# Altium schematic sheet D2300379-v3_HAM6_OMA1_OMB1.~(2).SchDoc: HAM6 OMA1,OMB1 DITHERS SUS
size C; Engineer: L. Sanchez; Organization: LIGO Laboratory; Address1: California Institute of Technology; Address2: Massachusetts Institute of Technology; DocumentNumber: D2300379; Revision: v2; SheetNumber: 2; SheetTotal: 9
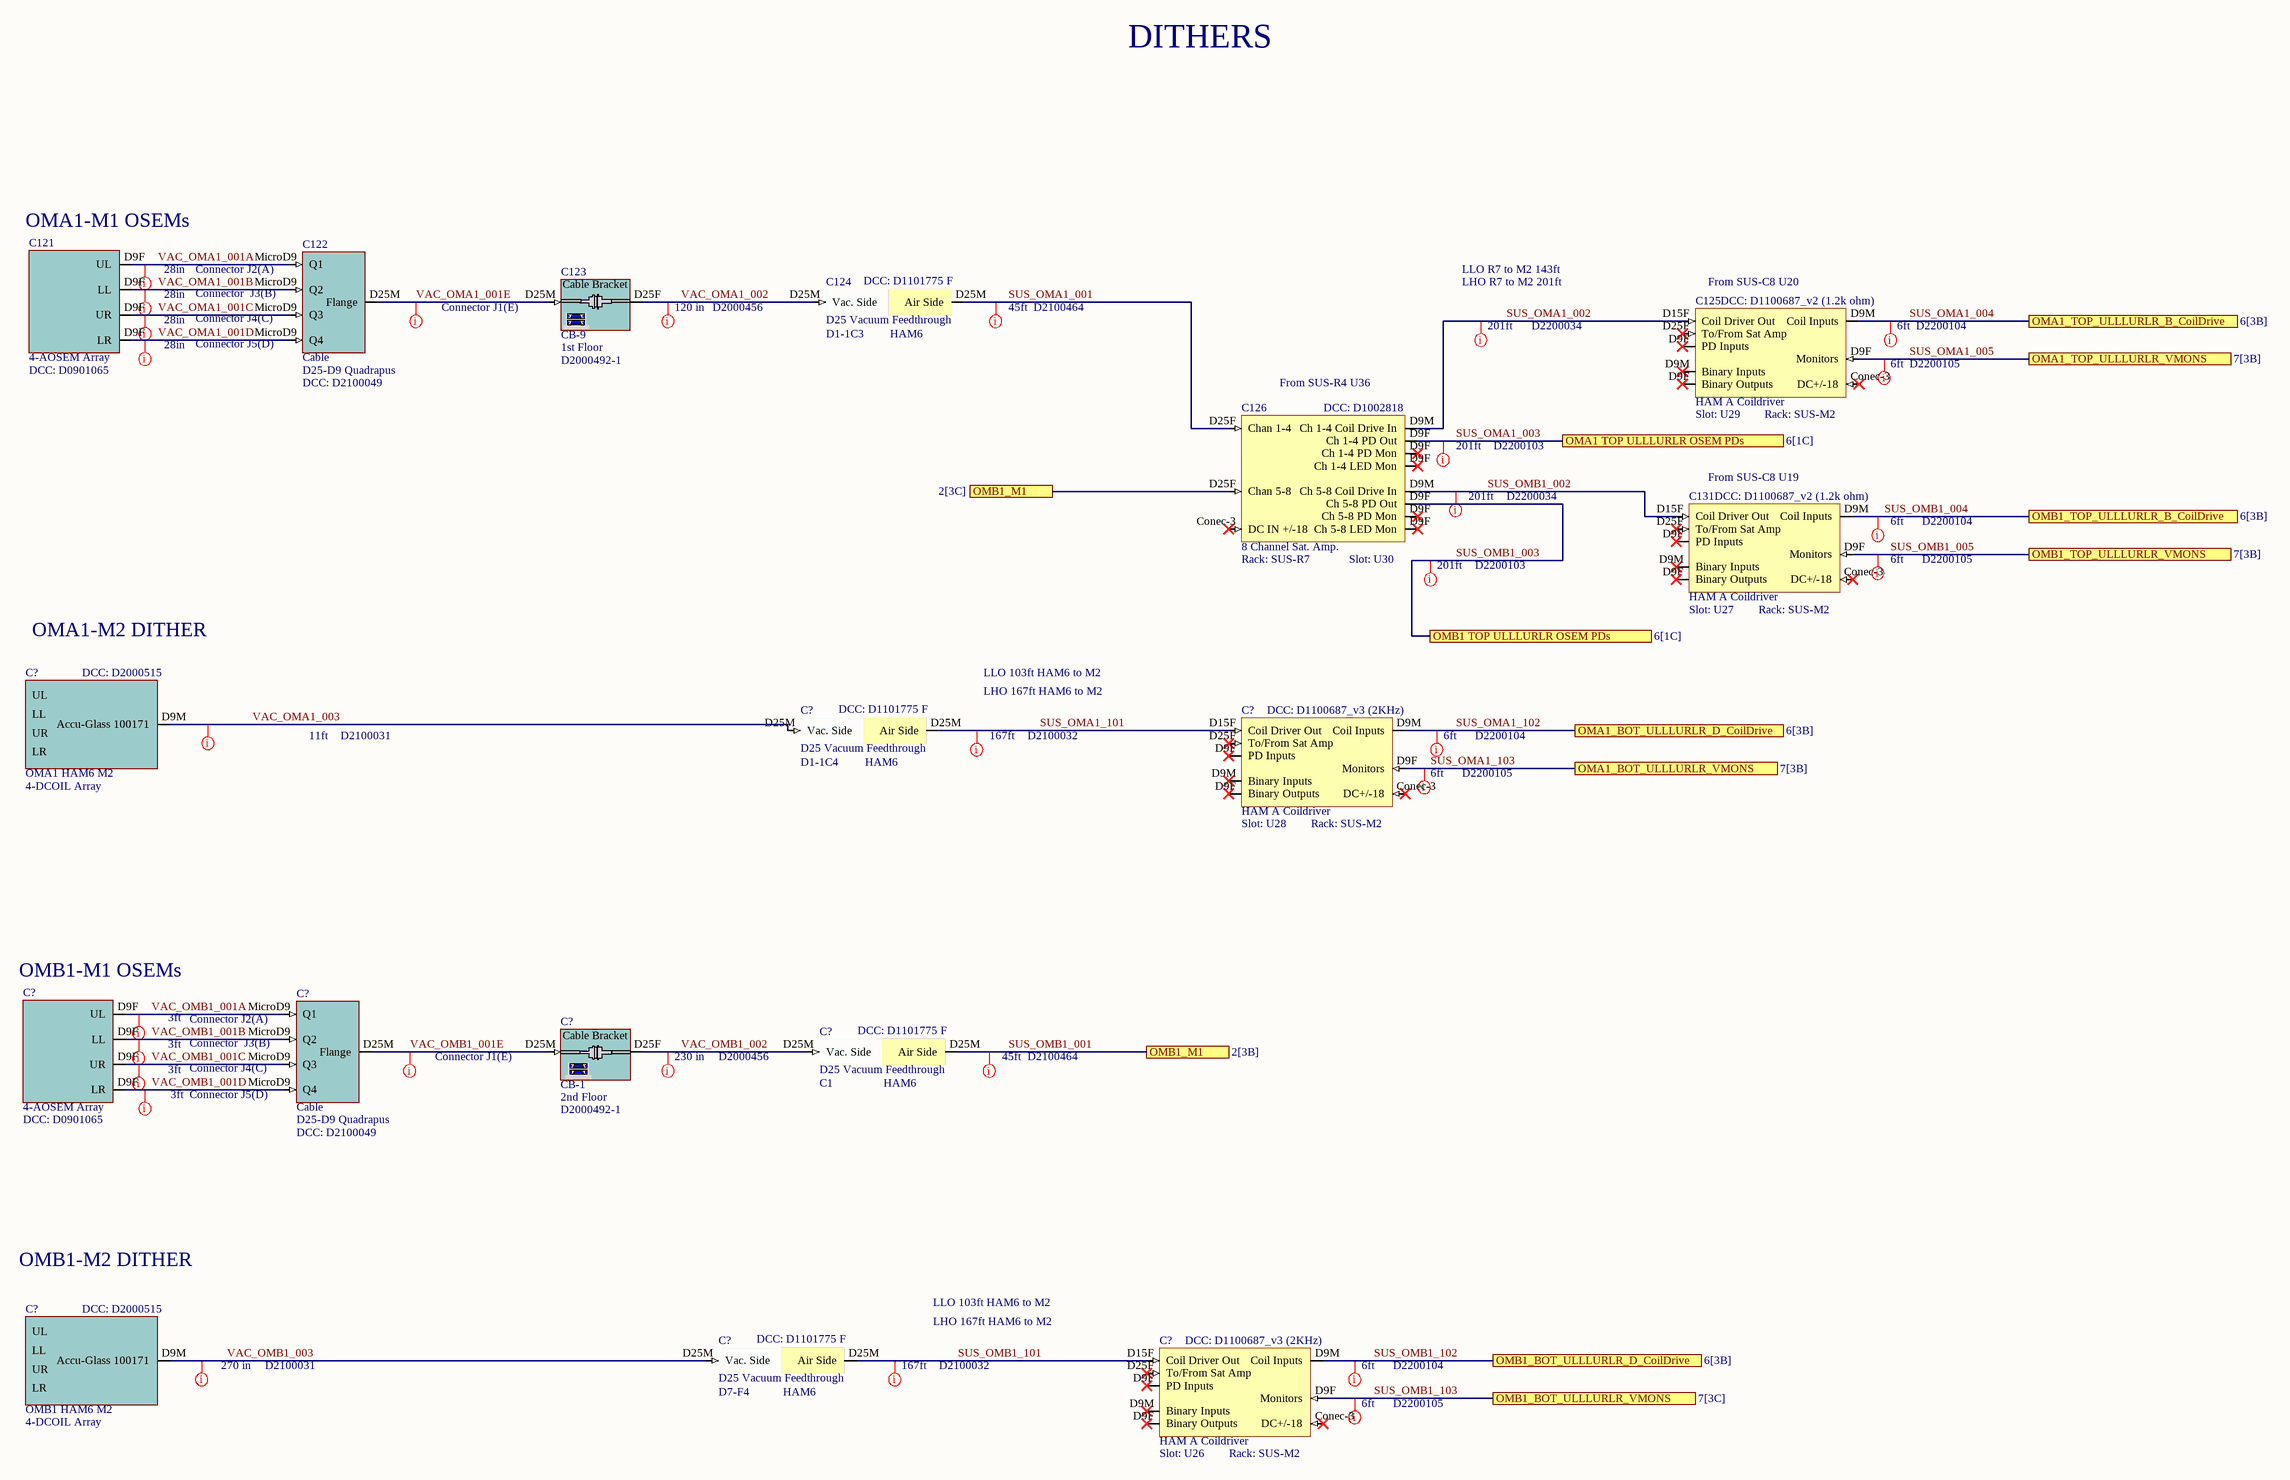
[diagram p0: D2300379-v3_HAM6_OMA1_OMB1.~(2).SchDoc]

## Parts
(Parts that share a designator on the sheet are numbered #1, #2 ... from top to bottom, then left to right.)
C121  4-AOSEM Array  DCC: D0901065
C122  Cable  value D25-D9 Quadrapus  DCC: D2100049
C123  Rack: CB-9  Slot: 1st Floor  DCC: D2000492-1  (hidden comment: Cable Bracket)
C124  D25 Vacuum Feedthrough  DCC: D1101775 F  Feedthrough: D1-1C3  Chamber: HAM6
C125  HAM A Coildriver  DCC: D1100687_v2 (1.2k ohm)  Rack: SUS-M2  Slot: U29
C126  8 Channel Sat. Amp.  DCC: D1002818  Rack: SUS-R7  Slot: U30
C131  HAM A Coildriver  DCC: D1100687_v2 (1.2k ohm)  Rack: SUS-M2  Slot: U27
C?#1  value 4-DCOIL Array  Rack: OMA1 HAM6 M2  DCC: D2000515  (hidden comment: Cable)
C?#2  D25 Vacuum Feedthrough  DCC: D1101775 F  Feedthrough: D1-1C4  Chamber: HAM6
C?#3  HAM A Coildriver  DCC: D1100687_v3 (2KHz)  Rack: SUS-M2  Slot: U28
C?#4  Rack: CB-1  Slot: 2nd Floor  DCC: D2000492-1  (hidden comment: Cable Bracket)
C?#5  D25 Vacuum Feedthrough  DCC: D1101775 F  Feedthrough: C1  Chamber: HAM6
C?#6  4-AOSEM Array  DCC: D0901065
C?#7  Cable  value D25-D9 Quadrapus  DCC: D2100049
C?#8  value 4-DCOIL Array  Rack: OMB1 HAM6 M2  DCC: D2000515  (hidden comment: Cable)
C?#9  D25 Vacuum Feedthrough  DCC: D1101775 F  Feedthrough: D7-F4  Chamber: HAM6
C?#10  HAM A Coildriver  DCC: D1100687_v3 (2KHz)  Rack: SUS-M2  Slot: U26

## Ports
OMA1 TOP ULLLURLR OSEM PDs (see 6[1C]), OMA1_BOT_ULLLURLR_D_CoilDrive (see 6[3B]), OMA1_BOT_ULLLURLR_VMONS (see 7[3B]), OMA1_TOP_ULLLURLR_B_CoilDrive (see 6[3B]), OMA1_TOP_ULLLURLR_VMONS (see 7[3B]), OMB1 TOP ULLLURLR OSEM PDs (see 6[1C]), OMB1_BOT_ULLLURLR_D_CoilDrive (see 6[3B]), OMB1_BOT_ULLLURLR_VMONS (see 7[3C]), OMB1_M1 (see 2[3B]), OMB1_M1 (see 2[3C]), OMB1_TOP_ULLLURLR_B_CoilDrive (see 6[3B]), OMB1_TOP_ULLLURLR_VMONS (see 7[3B])

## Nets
SUS_OMA1_001: C124.D25M(Air_Side) C126.D25F(Chan_1-4)
SUS_OMA1_002: C125.D15F(Coil_Driver_Out) C126.D9M(Ch_1-4_Coil_Drive_In)
SUS_OMA1_003: C126.D9F(Ch_1-4_PD_Out) ; port OMA1 TOP ULLLURLR OSEM PDs
SUS_OMA1_004: C125.D9M(Coil_Inputs) ; port OMA1_TOP_ULLLURLR_B_CoilDrive
SUS_OMA1_005: C125.D9F(PD_Inputs) ; port OMA1_TOP_ULLLURLR_VMONS
SUS_OMA1_101: C?#2.D25M(Air_Side) C?#3.D15F(Coil_Driver_Out)
SUS_OMA1_102: C?#3.D9M(Coil_Inputs) ; port OMA1_BOT_ULLLURLR_D_CoilDrive
SUS_OMA1_103: C?#3.D9F(PD_Inputs) ; port OMA1_BOT_ULLLURLR_VMONS
SUS_OMB1_001: C126.D25F(Chan_5-8) C?#5.D25M(Air_Side) ; port OMB1_M1
SUS_OMB1_002: C126.D9M(Ch_5-8_Coil_Drive_In) C131.D15F(Coil_Driver_Out)
SUS_OMB1_003: C126.D9F(Ch_5-8_PD_Out) ; port OMB1 TOP ULLLURLR OSEM PDs
SUS_OMB1_004: C131.D9M(Coil_Inputs) ; port OMB1_TOP_ULLLURLR_B_CoilDrive
SUS_OMB1_005: C131.D9F(PD_Inputs) ; port OMB1_TOP_ULLLURLR_VMONS
SUS_OMB1_101: C?#9.D25M(Air_Side) C?#10.D15F(Coil_Driver_Out)
SUS_OMB1_102: C?#10.D9M(Coil_Inputs) ; port OMB1_BOT_ULLLURLR_D_CoilDrive
SUS_OMB1_103: C?#10.D9F(PD_Inputs) ; port OMB1_BOT_ULLLURLR_VMONS
VAC_OMA1_001A: C121.D9F(UL) C122.MicroD9(Q1)
VAC_OMA1_001B: C121.D9F(LL) C122.MicroD9(Q2)
VAC_OMA1_001C: C121.D9F(UR) C122.MicroD9(Q3)
VAC_OMA1_001D: C121.D9F(LR) C122.MicroD9(Q4)
VAC_OMA1_001E: C122.D25M(Flange) C123.D25M
VAC_OMA1_002: C123.D25F C124.D25M(Vac._Side)
VAC_OMA1_003: C?#1.D9M(Accu-Glass_100171) C?#2.D25M(Vac._Side)
VAC_OMB1_001A: C?#6.D9F(UL) C?#7.MicroD9(Q1)
VAC_OMB1_001B: C?#6.D9F(LL) C?#7.MicroD9(Q2)
VAC_OMB1_001C: C?#6.D9F(UR) C?#7.MicroD9(Q3)
VAC_OMB1_001D: C?#6.D9F(LR) C?#7.MicroD9(Q4)
VAC_OMB1_001E: C?#4.D25M C?#7.D25M(Flange)
VAC_OMB1_002: C?#4.D25F C?#5.D25M(Vac._Side)
VAC_OMB1_003: C?#8.D9M(Accu-Glass_100171) C?#9.D25M(Vac._Side)

Not connected (* = marked no-connect by the designer): C125 Conec-3(DC+/-18)* D25F(To/From_Sat_Amp)*; C126 Conec-3(DC_IN_+/-18)*; C131 Conec-3(DC+/-18)* D25F(To/From_Sat_Amp)*; C?#3 Conec-3(DC+/-18)* D25F(To/From_Sat_Amp)*; C?#10 Conec-3(DC+/-18)* D25F(To/From_Sat_Amp)*

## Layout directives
Length: 28in; DCC: Connector J2(A): VAC_OMA1_001A
Length: 28in; DCC: Connector  J3(B): VAC_OMA1_001B
Length: 28in; DCC: Connector J4(C): VAC_OMA1_001C
Length: 201ft; DCC: D2200034: SUS_OMA1_002, SUS_OMB1_002
Length: 201ft; DCC: D2200103: SUS_OMA1_003, SUS_OMB1_003
Length: 5; DCC: Connector J1(E): VAC_OMA1_001E, VAC_OMB1_001E
Length: 120 in; DCC: D2000456: VAC_OMA1_002
Length: 6ft; DCC: D2200104: SUS_OMA1_004, SUS_OMA1_102, SUS_OMB1_004, SUS_OMB1_102
Length: 6ft; DCC: D2200105: SUS_OMA1_005, SUS_OMA1_103, SUS_OMB1_005, SUS_OMB1_103
Length: 45ft; DCC: D2100464: SUS_OMA1_001, SUS_OMB1_001
Length: 28in; DCC: Connector J5(D): VAC_OMA1_001D
Length: 167ft; DCC: D2100032: SUS_OMA1_101, SUS_OMB1_101
Length: 11ft; DCC: D2100031: VAC_OMA1_003
Length: 270 in; DCC: D2100031: VAC_OMB1_003
Length: 3ft; DCC: Connector J5(D): VAC_OMB1_001D
Length: 3ft; DCC: Connector J2(A): VAC_OMB1_001A
Length: 3ft; DCC: Connector  J3(B): VAC_OMB1_001B
Length: 3ft; DCC: Connector J4(C): VAC_OMB1_001C
Length: 230 in; DCC: D2000456: VAC_OMB1_002

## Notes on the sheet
- DITHERS
- (near C121) OMA1-M1 OSEMs
- LLO R7 to M2 143ft
- LHO R7 to M2 201ft
- (near C125) From SUS-C8 U20
- (near C126) From SUS-R4 U36
- (near C131) From SUS-C8 U19
- OMA1-M2 DITHER
- LLO 103ft HAM6 to M2
- LHO 167ft HAM6 to M2
- (near C?#6) OMB1-M1 OSEMs
- OMB1-M2 DITHER

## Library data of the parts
C121 = 4-BOSEM Array: Rack: SUS-R?; Serial: Sxxxxxxx; Slot: U?; System: SUS; Parameter: OMA1 HAM6 M1
C122 C?#7 = Flange: Rack: SUS-R?; Serial: Sxxxxxxx; Slot: U?; System: SUS
C123 = D1001347-2 1st Cable Bracket: D1001347-2 1/2 Cable Bracket for BSC Tables; Serial: Sxxxxxxx; System: SUS
C124 C?#2 C?#5 C?#9 = VacFeedD25: Serial: Sxxxxxxx; System: ISC; Rack: R?; Slot: U?
C125 C131 C?#3 C?#10 = HAM A Coildriver: Serial: Sxxxxxxx; System: ISC
C126 = 8 Channel Sat. Amp.: Serial: Sxxxxxxx; System: ISC
C?#1 C?#8 = COSEM Array: Serial: Sxxxxxxx; Slot: U?; System: SUS
C?#4 = D1001347-2 2nd Cable Bracket: D1001347-2 2/2 Cable Bracket for BSC Tables; Serial: Sxxxxxxx; System: SUS
C?#6 = 4-BOSEM Array: Rack: SUS-R?; Serial: Sxxxxxxx; Slot: U?; System: SUS; Parameter: OMB1 HAM6 M1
